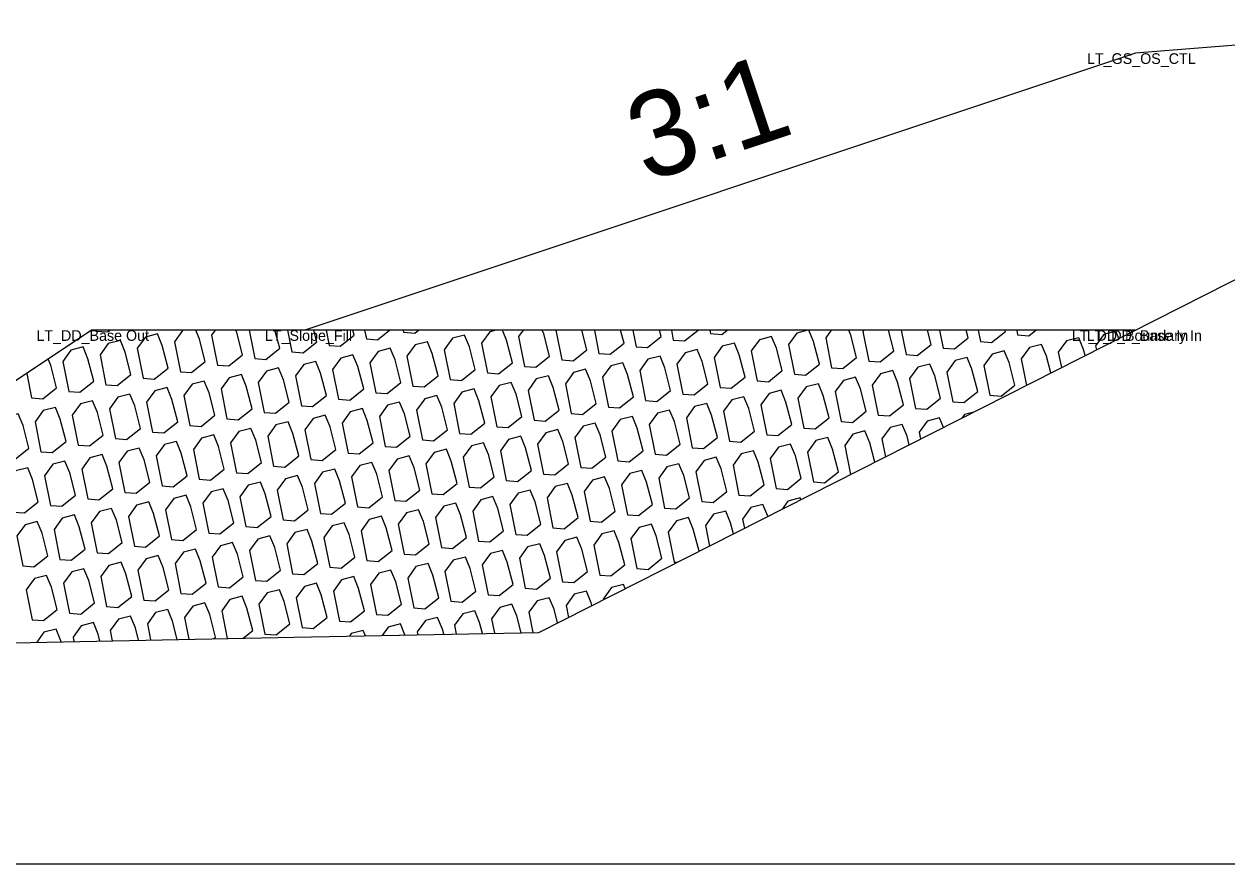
# Model space of a CAD drawing. Extents: x -26 to 203, y -10 to 20020.
# Drawn here: x 69.58 to 80.86, y 4500 to 4507.87 of the extents above; entities that cross this region are included whole.
import ezdxf

# ---------------------------------------------------------------- set-up
doc = ezdxf.new("R2010")
doc.units = 0
for name, color, linetype in [('Default', 7, 'Continuous'), ('Exist Cross Section Cell', 7, 'Continuous'), ('Exist XS Ground Line', 7, 'Continuous'), ('Old_Level_1', 7, 'Continuous'), ('Prop CMT Rip Rap Class II', 7, 'Continuous'), ('Prop CMT Slope Grass', 7, 'Continuous'), ('Prop XS Side Slope Text', 7, 'Continuous')]:
    doc.layers.add(name, color=color, linetype=linetype)

msp = doc.modelspace()

# ---------------------------------------------------------------- linework, layer by layer
at = {"layer": 'Exist Cross Section Cell'}
msp.add_line((0, 4500), (100, 4500), dxfattribs=at)
at = {"layer": 'Exist XS Ground Line'}
for p, q in [((74.409, 4502.168), (83.978, 4507.017)), ((35.166, 4501.376), (72.115, 4502.125)), ((72.115, 4502.125), (74.409, 4502.168))]:
    msp.add_line(p, q, dxfattribs=at)
at = {"layer": 'Old_Level_1'}
for p, q in [((70.261, 4505), (70.262, 4504.992)), ((71.693, 4505), (71.746, 4504.734)), ((72.054, 4505), (72.094, 4504.796)), ((72.415, 4505), (72.443, 4504.857)), ((72.775, 4505), (72.792, 4504.919)), ((73.136, 4505), (73.14, 4504.98)), ((74.568, 4505), (74.623, 4504.722)), ((74.929, 4505), (74.972, 4504.783)), ((75.29, 4505), (75.321, 4504.845)), ((75.651, 4505), (75.669, 4504.906)), ((76.011, 4505), (76.018, 4504.968)), ((77.804, 4505), (77.85, 4504.771)), ((78.165, 4505), (78.198, 4504.832)), ((78.526, 4505), (78.547, 4504.894)), ((78.887, 4505), (78.895, 4504.955)), ((69.609, 4504.594), (69.654, 4504.365)), ((75.676, 4502.828), (75.708, 4502.826))]:
    msp.add_line(p, q, dxfattribs=at)
for points in [[(70.262, 4504.992), (70.368, 4504.985), (70.387, 4505)], [(71.079, 4505), (71.07, 4504.998), (70.993, 4504.891), (71.049, 4504.611)], [(71.049, 4504.611), (71.154, 4504.604), (71.283, 4504.707), (71.229, 4504.917), (71.195, 4505)], [(71.376, 4505), (71.342, 4504.953), (71.397, 4504.673)], [(71.397, 4504.673), (71.502, 4504.665), (71.632, 4504.768), (71.577, 4504.979), (71.569, 4505)], [(71.746, 4504.734), (71.851, 4504.726), (71.981, 4504.83), (71.936, 4505)], [(72.094, 4504.796), (72.2, 4504.788), (72.329, 4504.891), (72.301, 4505)], [(72.443, 4504.857), (72.548, 4504.849), (72.678, 4504.953), (72.665, 4505)], [(72.792, 4504.919), (72.897, 4504.911), (73.009, 4505)], [(73.14, 4504.98), (73.245, 4504.972), (73.28, 4505)], [(74.005, 4505), (73.948, 4504.985), (73.871, 4504.879), (73.926, 4504.599)], [(73.926, 4504.599), (74.031, 4504.591), (74.161, 4504.694), (74.107, 4504.905), (74.067, 4505)], [(74.262, 4505), (74.219, 4504.94), (74.275, 4504.66)], [(74.275, 4504.66), (74.38, 4504.653), (74.51, 4504.756), (74.455, 4504.966), (74.441, 4505)], [(74.623, 4504.722), (74.729, 4504.714), (74.858, 4504.817), (74.811, 4505)], [(74.972, 4504.783), (75.077, 4504.776), (75.207, 4504.879), (75.175, 4505)], [(75.321, 4504.845), (75.426, 4504.837), (75.555, 4504.94), (75.54, 4505)], [(75.669, 4504.906), (75.774, 4504.899), (75.902, 4505)], [(76.018, 4504.968), (76.123, 4504.96), (76.173, 4505)], [(76.93, 4505), (76.825, 4504.973), (76.748, 4504.867), (76.804, 4504.587)], [(76.804, 4504.587), (76.909, 4504.579), (77.039, 4504.682), (76.984, 4504.893), (76.94, 4505)], [(77.149, 4505), (77.097, 4504.928), (77.152, 4504.648)], [(77.152, 4504.648), (77.258, 4504.64), (77.387, 4504.744), (77.333, 4504.954), (77.314, 4505)], [(77.453, 4505), (77.445, 4504.989), (77.501, 4504.709)], [(77.501, 4504.709), (77.606, 4504.702), (77.736, 4504.805), (77.685, 4505)], [(77.85, 4504.771), (77.955, 4504.763), (78.084, 4504.867), (78.05, 4505)], [(78.198, 4504.832), (78.303, 4504.825), (78.433, 4504.928), (78.414, 4505)], [(78.547, 4504.894), (78.652, 4504.886), (78.782, 4504.989), (78.779, 4505)], [(78.895, 4504.955), (79.001, 4504.948), (79.066, 4505)], [(79.845, 4504.922), (79.817, 4504.99), (79.703, 4504.961), (79.626, 4504.854), (79.634, 4504.815)], [(70.351, 4504.488), (70.457, 4504.481), (70.586, 4504.584), (70.532, 4504.794), (70.487, 4504.904), (70.373, 4504.875), (70.296, 4504.768), (70.351, 4504.488)], [(79.206, 4504.599), (79.165, 4504.757), (79.12, 4504.867), (79.006, 4504.838), (78.929, 4504.731), (78.978, 4504.483)], [(79.528, 4504.762), (79.513, 4504.819), (79.468, 4504.929), (79.354, 4504.899), (79.277, 4504.793), (79.306, 4504.649)], [(69.654, 4504.365), (69.759, 4504.358), (69.889, 4504.461), (69.835, 4504.671), (69.811, 4504.729)], [(70.789, 4504.046), (70.894, 4504.038), (71.024, 4504.141), (70.969, 4504.352), (70.924, 4504.462), (70.81, 4504.432), (70.733, 4504.326), (70.789, 4504.046)], [(78.2, 4504.089), (78.163, 4504.179), (78.049, 4504.149), (77.972, 4504.043), (77.984, 4503.98)], [(78.485, 4504.233), (78.397, 4504.211), (78.373, 4504.176)], [(77.558, 4503.764), (77.511, 4503.946), (77.465, 4504.056), (77.352, 4504.026), (77.275, 4503.92), (77.329, 4503.648)], [(77.88, 4503.927), (77.859, 4504.007), (77.814, 4504.117), (77.7, 4504.088), (77.623, 4503.981), (77.656, 4503.814)], [(70.878, 4503.542), (70.983, 4503.534), (71.113, 4503.637), (71.058, 4503.848), (71.013, 4503.957), (70.899, 4503.928), (70.822, 4503.822), (70.878, 4503.542)], [(71.315, 4503.099), (71.42, 4503.091), (71.55, 4503.195), (71.496, 4503.405), (71.45, 4503.515), (71.337, 4503.485), (71.26, 4503.379), (71.315, 4503.099)], [(76.554, 4503.255), (76.554, 4503.258), (76.509, 4503.367), (76.395, 4503.338), (76.318, 4503.231), (76.335, 4503.144)], [(76.864, 4503.412), (76.857, 4503.429), (76.743, 4503.399), (76.688, 4503.323)], [(75.91, 4502.929), (75.856, 4503.135), (75.811, 4503.244), (75.698, 4503.215), (75.62, 4503.108), (75.676, 4502.828)], [(76.232, 4503.092), (76.205, 4503.196), (76.16, 4503.306), (76.046, 4503.276), (75.969, 4503.17), (76.007, 4502.978)], [(71.753, 4502.656), (71.858, 4502.649), (71.987, 4502.752), (71.933, 4502.963), (71.888, 4503.072), (71.774, 4503.043), (71.697, 4502.936), (71.753, 4502.656)], [(71.404, 4502.595), (71.509, 4502.587), (71.639, 4502.69), (71.584, 4502.901), (71.539, 4503.011), (71.426, 4502.981), (71.348, 4502.875), (71.404, 4502.595)], [(71.842, 4502.152), (71.947, 4502.145), (72.076, 4502.248), (72.022, 4502.458), (71.977, 4502.568), (71.863, 4502.539), (71.786, 4502.432), (71.842, 4502.152)], [(75.219, 4502.579), (75.203, 4502.617), (75.089, 4502.588), (75.012, 4502.481), (75.014, 4502.474)], [(71.639, 4502.115), (71.728, 4502.186), (71.673, 4502.397), (71.628, 4502.507), (71.514, 4502.477), (71.437, 4502.371), (71.489, 4502.112)], [(74.584, 4502.257), (74.551, 4502.385), (74.506, 4502.494), (74.392, 4502.465), (74.315, 4502.359), (74.353, 4502.167)], [(74.906, 4502.42), (74.9, 4502.446), (74.854, 4502.556), (74.741, 4502.526), (74.664, 4502.42), (74.686, 4502.308)], [(71.02, 4502.103), (70.976, 4502.274), (70.931, 4502.384), (70.817, 4502.354), (70.74, 4502.248), (70.77, 4502.098)], [(71.36, 4502.11), (71.379, 4502.125), (71.325, 4502.336), (71.28, 4502.445), (71.166, 4502.416), (71.089, 4502.309), (71.129, 4502.105)], [(73.88, 4502.158), (73.854, 4502.262), (73.809, 4502.371), (73.695, 4502.342), (73.618, 4502.236), (73.634, 4502.154)], [(74.243, 4502.165), (74.202, 4502.323), (74.157, 4502.433), (74.043, 4502.403), (73.966, 4502.297), (73.993, 4502.161)], [(70.295, 4502.088), (70.279, 4502.151), (70.234, 4502.261), (70.12, 4502.231), (70.043, 4502.125), (70.051, 4502.083)], [(70.658, 4502.096), (70.628, 4502.213), (70.582, 4502.322), (70.469, 4502.293), (70.392, 4502.186), (70.411, 4502.091)], [(73.154, 4502.145), (73.111, 4502.248), (72.998, 4502.219), (72.941, 4502.141)], [(73.518, 4502.152), (73.505, 4502.2), (73.46, 4502.31), (73.346, 4502.281), (73.269, 4502.174), (73.275, 4502.147)], [(69.933, 4502.081), (69.93, 4502.09), (69.885, 4502.199), (69.771, 4502.17), (69.704, 4502.076)], [(72.783, 4502.138), (72.763, 4502.187), (72.649, 4502.158), (72.633, 4502.135)]]:
    msp.add_lwpolyline(points, dxfattribs=at)
for points in [[(70.7, 4504.55), (70.805, 4504.542), (70.935, 4504.645), (70.88, 4504.856), (70.835, 4504.966), (70.721, 4504.936), (70.644, 4504.83)], [(73.578, 4504.537), (73.683, 4504.53), (73.812, 4504.633), (73.758, 4504.844), (73.713, 4504.953), (73.599, 4504.924), (73.522, 4504.817)], [(76.455, 4504.525), (76.561, 4504.517), (76.69, 4504.621), (76.636, 4504.831), (76.59, 4504.941), (76.477, 4504.911), (76.4, 4504.805)], [(70.003, 4504.427), (70.108, 4504.419), (70.238, 4504.522), (70.183, 4504.733), (70.138, 4504.843), (70.024, 4504.813), (69.947, 4504.707)], [(72.88, 4504.414), (72.986, 4504.407), (73.115, 4504.51), (73.061, 4504.721), (73.016, 4504.83), (72.902, 4504.801), (72.825, 4504.694)], [(73.229, 4504.476), (73.334, 4504.468), (73.464, 4504.572), (73.409, 4504.782), (73.364, 4504.892), (73.25, 4504.862), (73.173, 4504.756)], [(75.758, 4504.402), (75.863, 4504.394), (75.993, 4504.498), (75.938, 4504.708), (75.893, 4504.818), (75.78, 4504.789), (75.702, 4504.682)], [(76.107, 4504.464), (76.212, 4504.456), (76.341, 4504.559), (76.287, 4504.77), (76.242, 4504.879), (76.128, 4504.85), (76.051, 4504.744)], [(72.183, 4504.292), (72.288, 4504.284), (72.418, 4504.387), (72.364, 4504.598), (72.318, 4504.707), (72.205, 4504.678), (72.128, 4504.572)], [(72.532, 4504.353), (72.637, 4504.345), (72.767, 4504.449), (72.712, 4504.659), (72.667, 4504.769), (72.553, 4504.739), (72.476, 4504.633)], [(75.409, 4504.341), (75.515, 4504.333), (75.644, 4504.436), (75.59, 4504.647), (75.545, 4504.757), (75.431, 4504.727), (75.354, 4504.621)], [(78.287, 4504.328), (78.392, 4504.321), (78.522, 4504.424), (78.467, 4504.634), (78.422, 4504.744), (78.309, 4504.715), (78.231, 4504.608)], [(78.636, 4504.39), (78.741, 4504.382), (78.871, 4504.485), (78.816, 4504.696), (78.771, 4504.806), (78.657, 4504.776), (78.58, 4504.67)], [(71.835, 4504.23), (71.94, 4504.222), (72.069, 4504.326), (72.015, 4504.536), (71.97, 4504.646), (71.856, 4504.616), (71.779, 4504.51)], [(74.712, 4504.218), (74.818, 4504.21), (74.947, 4504.313), (74.893, 4504.524), (74.847, 4504.634), (74.734, 4504.604), (74.657, 4504.498)], [(75.061, 4504.279), (75.166, 4504.272), (75.296, 4504.375), (75.241, 4504.585), (75.196, 4504.695), (75.082, 4504.666), (75.005, 4504.559)], [(77.59, 4504.205), (77.695, 4504.198), (77.825, 4504.301), (77.77, 4504.512), (77.725, 4504.621), (77.611, 4504.592), (77.534, 4504.485)], [(77.939, 4504.267), (78.044, 4504.259), (78.173, 4504.362), (78.119, 4504.573), (78.074, 4504.683), (77.96, 4504.653), (77.883, 4504.547)], [(71.137, 4504.107), (71.243, 4504.099), (71.372, 4504.203), (71.318, 4504.413), (71.273, 4504.523), (71.159, 4504.494), (71.082, 4504.387)], [(71.486, 4504.169), (71.591, 4504.161), (71.721, 4504.264), (71.666, 4504.475), (71.621, 4504.584), (71.507, 4504.555), (71.43, 4504.449)], [(74.015, 4504.095), (74.12, 4504.087), (74.25, 4504.19), (74.195, 4504.401), (74.15, 4504.511), (74.037, 4504.481), (73.959, 4504.375)], [(74.364, 4504.156), (74.469, 4504.149), (74.598, 4504.252), (74.544, 4504.462), (74.499, 4504.572), (74.385, 4504.543), (74.308, 4504.436)], [(76.893, 4504.082), (76.998, 4504.075), (77.128, 4504.178), (77.073, 4504.389), (77.028, 4504.498), (76.914, 4504.469), (76.837, 4504.362)], [(77.241, 4504.144), (77.347, 4504.136), (77.476, 4504.24), (77.422, 4504.45), (77.377, 4504.56), (77.263, 4504.53), (77.186, 4504.424)], [(70.44, 4503.984), (70.545, 4503.977), (70.675, 4504.08), (70.621, 4504.29), (70.575, 4504.4), (70.462, 4504.371), (70.385, 4504.264)], [(73.318, 4503.972), (73.423, 4503.964), (73.553, 4504.067), (73.498, 4504.278), (73.453, 4504.388), (73.339, 4504.358), (73.262, 4504.252)], [(73.666, 4504.033), (73.772, 4504.026), (73.901, 4504.129), (73.847, 4504.339), (73.802, 4504.449), (73.688, 4504.42), (73.611, 4504.313)], [(76.196, 4503.96), (76.301, 4503.952), (76.43, 4504.055), (76.376, 4504.266), (76.331, 4504.375), (76.217, 4504.346), (76.14, 4504.24)], [(76.544, 4504.021), (76.649, 4504.013), (76.779, 4504.117), (76.724, 4504.327), (76.679, 4504.437), (76.566, 4504.407), (76.489, 4504.301)], [(69.743, 4503.861), (69.848, 4503.854), (69.978, 4503.957), (69.923, 4504.167), (69.878, 4504.277), (69.764, 4504.248), (69.687, 4504.141)], [(70.092, 4503.923), (70.197, 4503.915), (70.326, 4504.018), (70.272, 4504.229), (70.227, 4504.339), (70.113, 4504.309), (70.036, 4504.203)], [(72.621, 4503.849), (72.726, 4503.841), (72.855, 4503.945), (72.801, 4504.155), (72.756, 4504.265), (72.642, 4504.235), (72.565, 4504.129)], [(72.969, 4503.91), (73.075, 4503.903), (73.204, 4504.006), (73.15, 4504.217), (73.104, 4504.326), (72.991, 4504.297), (72.914, 4504.19)], [(75.498, 4503.837), (75.604, 4503.829), (75.733, 4503.932), (75.679, 4504.143), (75.634, 4504.252), (75.52, 4504.223), (75.443, 4504.117)], [(75.847, 4503.898), (75.952, 4503.89), (76.082, 4503.994), (76.027, 4504.204), (75.982, 4504.314), (75.868, 4504.284), (75.791, 4504.178)], [(69.394, 4503.8), (69.5, 4503.792), (69.629, 4503.895), (69.575, 4504.106), (69.53, 4504.216), (69.416, 4504.186), (69.339, 4504.08)], [(71.923, 4503.726), (72.029, 4503.718), (72.158, 4503.822), (72.104, 4504.032), (72.059, 4504.142), (71.945, 4504.112), (71.868, 4504.006)], [(72.272, 4503.787), (72.377, 4503.78), (72.507, 4503.883), (72.452, 4504.094), (72.407, 4504.203), (72.294, 4504.174), (72.216, 4504.067)], [(75.15, 4503.775), (75.255, 4503.767), (75.385, 4503.871), (75.33, 4504.081), (75.285, 4504.191), (75.171, 4504.162), (75.094, 4504.055)], [(71.575, 4503.665), (71.68, 4503.657), (71.81, 4503.76), (71.755, 4503.971), (71.71, 4504.08), (71.596, 4504.051), (71.519, 4503.945)], [(74.453, 4503.652), (74.558, 4503.645), (74.687, 4503.748), (74.633, 4503.958), (74.588, 4504.068), (74.474, 4504.039), (74.397, 4503.932)], [(74.801, 4503.714), (74.906, 4503.706), (75.036, 4503.809), (74.982, 4504.02), (74.936, 4504.13), (74.823, 4504.1), (74.746, 4503.994)], [(71.226, 4503.603), (71.332, 4503.595), (71.461, 4503.699), (71.407, 4503.909), (71.362, 4504.019), (71.248, 4503.989), (71.171, 4503.883)], [(73.755, 4503.529), (73.861, 4503.522), (73.99, 4503.625), (73.936, 4503.835), (73.891, 4503.945), (73.777, 4503.916), (73.7, 4503.809)], [(74.104, 4503.591), (74.209, 4503.583), (74.339, 4503.686), (74.284, 4503.897), (74.239, 4504.007), (74.125, 4503.977), (74.048, 4503.871)], [(76.633, 4503.517), (76.738, 4503.509), (76.868, 4503.613), (76.813, 4503.823), (76.768, 4503.933), (76.654, 4503.903), (76.577, 4503.797)], [(76.982, 4503.578), (77.087, 4503.571), (77.216, 4503.674), (77.162, 4503.885), (77.117, 4503.994), (77.003, 4503.965), (76.926, 4503.858)], [(70.181, 4503.419), (70.286, 4503.411), (70.415, 4503.514), (70.361, 4503.725), (70.316, 4503.834), (70.202, 4503.805), (70.125, 4503.699)], [(70.529, 4503.48), (70.634, 4503.472), (70.764, 4503.576), (70.709, 4503.786), (70.664, 4503.896), (70.551, 4503.867), (70.473, 4503.76)], [(73.058, 4503.406), (73.163, 4503.399), (73.293, 4503.502), (73.239, 4503.712), (73.193, 4503.822), (73.08, 4503.793), (73.003, 4503.686)], [(73.407, 4503.468), (73.512, 4503.46), (73.642, 4503.563), (73.587, 4503.774), (73.542, 4503.884), (73.428, 4503.854), (73.351, 4503.748)], [(75.936, 4503.394), (76.041, 4503.386), (76.171, 4503.49), (76.116, 4503.7), (76.071, 4503.81), (75.957, 4503.78), (75.88, 4503.674)], [(76.284, 4503.455), (76.39, 4503.448), (76.519, 4503.551), (76.465, 4503.762), (76.42, 4503.871), (76.306, 4503.842), (76.229, 4503.735)], [(69.483, 4503.296), (69.589, 4503.288), (69.718, 4503.391), (69.664, 4503.602), (69.619, 4503.712), (69.505, 4503.682), (69.428, 4503.576)], [(69.832, 4503.357), (69.937, 4503.35), (70.067, 4503.453), (70.012, 4503.663), (69.967, 4503.773), (69.853, 4503.744), (69.776, 4503.637)], [(72.361, 4503.283), (72.466, 4503.276), (72.596, 4503.379), (72.541, 4503.59), (72.496, 4503.699), (72.382, 4503.67), (72.305, 4503.563)], [(72.71, 4503.345), (72.815, 4503.337), (72.944, 4503.44), (72.89, 4503.651), (72.845, 4503.761), (72.731, 4503.731), (72.654, 4503.625)], [(75.587, 4503.333), (75.692, 4503.325), (75.822, 4503.428), (75.768, 4503.639), (75.722, 4503.748), (75.609, 4503.719), (75.532, 4503.613)], [(71.664, 4503.16), (71.769, 4503.153), (71.899, 4503.256), (71.844, 4503.467), (71.799, 4503.576), (71.685, 4503.547), (71.608, 4503.44)], [(72.012, 4503.222), (72.118, 4503.214), (72.247, 4503.317), (72.193, 4503.528), (72.148, 4503.638), (72.034, 4503.608), (71.957, 4503.502)], [(74.89, 4503.21), (74.995, 4503.202), (75.125, 4503.305), (75.07, 4503.516), (75.025, 4503.625), (74.911, 4503.596), (74.834, 4503.49)], [(75.239, 4503.271), (75.344, 4503.263), (75.473, 4503.367), (75.419, 4503.577), (75.374, 4503.687), (75.26, 4503.657), (75.183, 4503.551)], [(74.193, 4503.087), (74.298, 4503.079), (74.428, 4503.182), (74.373, 4503.393), (74.328, 4503.502), (74.214, 4503.473), (74.137, 4503.367)], [(74.541, 4503.148), (74.647, 4503.14), (74.776, 4503.244), (74.722, 4503.454), (74.677, 4503.564), (74.563, 4503.535), (74.486, 4503.428)], [(70.618, 4502.976), (70.723, 4502.968), (70.853, 4503.072), (70.798, 4503.282), (70.753, 4503.392), (70.639, 4503.362), (70.562, 4503.256)], [(70.967, 4503.038), (71.072, 4503.03), (71.201, 4503.133), (71.147, 4503.344), (71.102, 4503.453), (70.988, 4503.424), (70.911, 4503.318)], [(73.496, 4502.964), (73.601, 4502.956), (73.73, 4503.059), (73.676, 4503.27), (73.631, 4503.38), (73.517, 4503.35), (73.44, 4503.244)], [(73.844, 4503.025), (73.949, 4503.018), (74.079, 4503.121), (74.025, 4503.331), (73.979, 4503.441), (73.866, 4503.412), (73.789, 4503.305)], [(69.921, 4502.853), (70.026, 4502.845), (70.156, 4502.949), (70.101, 4503.159), (70.056, 4503.269), (69.942, 4503.24), (69.865, 4503.133)], [(70.269, 4502.915), (70.375, 4502.907), (70.504, 4503.01), (70.45, 4503.221), (70.405, 4503.33), (70.291, 4503.301), (70.214, 4503.195)], [(72.798, 4502.841), (72.904, 4502.833), (73.033, 4502.936), (72.979, 4503.147), (72.934, 4503.257), (72.82, 4503.227), (72.743, 4503.121)], [(73.147, 4502.902), (73.252, 4502.895), (73.382, 4502.998), (73.327, 4503.208), (73.282, 4503.318), (73.168, 4503.289), (73.091, 4503.182)], [(69.572, 4502.792), (69.677, 4502.784), (69.807, 4502.887), (69.753, 4503.098), (69.707, 4503.207), (69.594, 4503.178), (69.517, 4503.072)], [(72.101, 4502.718), (72.207, 4502.71), (72.336, 4502.813), (72.282, 4503.024), (72.236, 4503.134), (72.123, 4503.104), (72.046, 4502.998)], [(72.45, 4502.779), (72.555, 4502.772), (72.685, 4502.875), (72.63, 4503.085), (72.585, 4503.195), (72.471, 4503.166), (72.394, 4503.059)], [(75.328, 4502.767), (75.433, 4502.759), (75.562, 4502.863), (75.508, 4503.073), (75.463, 4503.183), (75.349, 4503.153), (75.272, 4503.047)], [(74.63, 4502.644), (74.736, 4502.636), (74.865, 4502.74), (74.811, 4502.95), (74.766, 4503.06), (74.652, 4503.03), (74.575, 4502.924)], [(74.979, 4502.706), (75.084, 4502.698), (75.214, 4502.801), (75.159, 4503.012), (75.114, 4503.121), (75, 4503.092), (74.923, 4502.986)], [(71.055, 4502.533), (71.161, 4502.526), (71.29, 4502.629), (71.236, 4502.84), (71.191, 4502.949), (71.077, 4502.92), (71, 4502.813)], [(73.933, 4502.521), (74.038, 4502.513), (74.168, 4502.617), (74.113, 4502.827), (74.068, 4502.937), (73.955, 4502.908), (73.878, 4502.801)], [(74.282, 4502.583), (74.387, 4502.575), (74.517, 4502.678), (74.462, 4502.889), (74.417, 4502.998), (74.303, 4502.969), (74.226, 4502.863)], [(70.358, 4502.411), (70.464, 4502.403), (70.593, 4502.506), (70.539, 4502.717), (70.493, 4502.826), (70.38, 4502.797), (70.303, 4502.691)], [(70.707, 4502.472), (70.812, 4502.464), (70.942, 4502.568), (70.887, 4502.778), (70.842, 4502.888), (70.728, 4502.858), (70.651, 4502.752)], [(73.236, 4502.398), (73.341, 4502.391), (73.471, 4502.494), (73.416, 4502.704), (73.371, 4502.814), (73.257, 4502.785), (73.18, 4502.678)], [(73.585, 4502.46), (73.69, 4502.452), (73.819, 4502.555), (73.765, 4502.766), (73.72, 4502.875), (73.606, 4502.846), (73.529, 4502.74)], [(69.661, 4502.288), (69.766, 4502.28), (69.896, 4502.383), (69.841, 4502.594), (69.796, 4502.703), (69.683, 4502.674), (69.605, 4502.568)], [(70.01, 4502.349), (70.115, 4502.341), (70.244, 4502.445), (70.19, 4502.655), (70.145, 4502.765), (70.031, 4502.735), (69.954, 4502.629)], [(72.539, 4502.275), (72.644, 4502.268), (72.774, 4502.371), (72.719, 4502.581), (72.674, 4502.691), (72.56, 4502.662), (72.483, 4502.555)], [(72.887, 4502.337), (72.993, 4502.329), (73.122, 4502.432), (73.068, 4502.643), (73.023, 4502.753), (72.909, 4502.723), (72.832, 4502.617)], [(72.19, 4502.214), (72.295, 4502.206), (72.425, 4502.309), (72.37, 4502.52), (72.325, 4502.63), (72.212, 4502.6), (72.135, 4502.494)]]:
    msp.add_lwpolyline(points, close=True, dxfattribs=at)
at = {"layer": 'Prop CMT Rip Rap Class II'}
for points in [[(79.998, 4505), (70.217, 4505), (65.71, 4501.995)], [(79.998, 4505), (79.998, 4505)]]:
    msp.add_lwpolyline(points, dxfattribs=at)
at = {"layer": 'Prop CMT Slope Grass'}
for points in [[(83.417, 4507.867), (80, 4507.594)], [(80, 4507.594), (72.217, 4505)]]:
    msp.add_lwpolyline(points, dxfattribs=at)

# ---------------------------------------------------------------- texts
at = {"layer": 'Default'}
for s, p in [('LT_GS_OS_CTL', (79.546, 4507.494)), ('LT_DD_Base Out', (69.7, 4504.9)), ('LT_Slope_Fill', (71.841, 4504.9)), ('LT_DD_Boundary In', (79.404, 4504.9)), ('LT_DD_Base In', (79.543, 4504.9))]:
    msp.add_text(s, height=0.1, dxfattribs=at).set_placement(p)
at = {"layer": 'Prop XS Side Slope Text'}
msp.add_text('3:1', height=0.8, rotation=18.4332, dxfattribs=at).set_placement((75.412, 4506.381))

doc.saveas('drawing.dxf')
